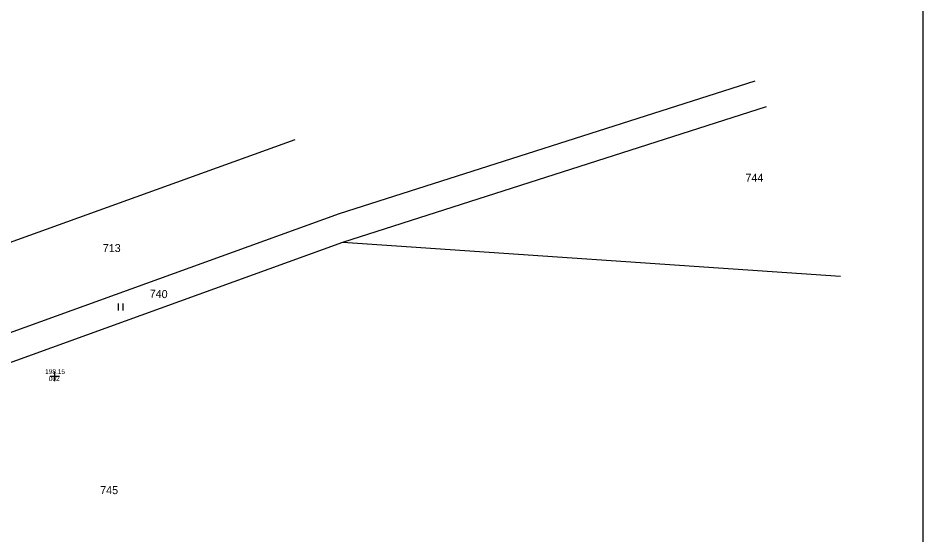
# Model space of a CAD drawing. Extents: x -706655 to -706193, y -1036183 to -1035040.
# Drawn here: x -706382.9 to -706286.8, y -1035230.4 to -1035175.5 of the extents above; entities that cross this region are included whole.
import ezdxf

# ---------------------------------------------------------------- set-up
doc = ezdxf.new("R2010")
doc.units = 0
for name, color, linetype in [('Hranice parcel', 7, 'Continuous'), ('křížky', 7, 'Continuous'), ('Parcelní čísla', 7, 'Continuous'), ('Vrstva 54', 7, 'Continuous'), ('výšky', 7, 'Continuous'), ('Značky kultur', 7, 'Continuous'), ('čísla bodu', 7, 'Continuous')]:
    doc.layers.add(name, color=color, linetype=linetype)

msp = doc.modelspace()

# ---------------------------------------------------------------- linework, layer by layer
at = {"layer": 'Hranice parcel'}
msp.add_line((-706387.38, -1035213.42), (-706348.39, -1035199.33), dxfattribs=at)
for points in [[(-706388.41, -1035210.6), (-706348.72, -1035196.28), (-706304.613, -1035182.15)], [(-706348.39, -1035199.33), (-706303.391, -1035184.909)], [(-706393.32, -1035202.8), (-706353.44, -1035188.416)], [(-706348.39, -1035199.33), (-706295.531, -1035202.911)]]:
    msp.add_lwpolyline(points, dxfattribs=at)
at = {"layer": 'křížky'}
for p, q in [((-706379.47, -1035213.57), (-706378.47, -1035213.57)), ((-706378.97, -1035214.07), (-706378.97, -1035213.07)), ((-706378.97, -1035213.57), (-706378.97, -1035213.57))]:
    msp.add_line(p, q, dxfattribs=at)
at = {"layer": 'Vrstva 54'}
msp.add_lwpolyline([(-706654.6, -1035040.151), (-706286.789, -1035040.151), (-706286.789, -1035285.37), (-706654.6, -1035285.37)], close=True, dxfattribs=at)
at = {"layer": 'Značky kultur'}
for p, q in [((-706372.202, -1035206.58), (-706372.202, -1035205.83)), ((-706371.701, -1035206.58), (-706371.701, -1035205.83))]:
    msp.add_line(p, q, dxfattribs=at)
at = {"layer": 'čísla bodu'}
for p, q in [((-706379.47, -1035213.57), (-706378.47, -1035213.57)), ((-706378.97, -1035214.07), (-706378.97, -1035213.07)), ((-706378.97, -1035213.57), (-706378.97, -1035213.57))]:
    msp.add_line(p, q, dxfattribs=at)

# ---------------------------------------------------------------- texts
at = {"layer": 'Parcelní čísla'}
for s, p in [('744', (-706305.627, -1035192.885)), ('713', (-706373.866, -1035200.365)), ('745', (-706374.14, -1035226.095))]:
    msp.add_text(s, height=0.85, dxfattribs=at).set_placement(p)
msp.add_text('740', height=0.85, rotation=358, dxfattribs=at).set_placement((-706368.895, -1035205.201))
at = {"layer": 'výšky'}
msp.add_text('198.15', height=0.5, dxfattribs=at).set_placement((-706379.992, -1035213.32))
at = {"layer": 'čísla bodu'}
msp.add_text('002', height=0.5, dxfattribs=at).set_placement((-706379.604, -1035214.07))

doc.saveas('drawing.dxf')
